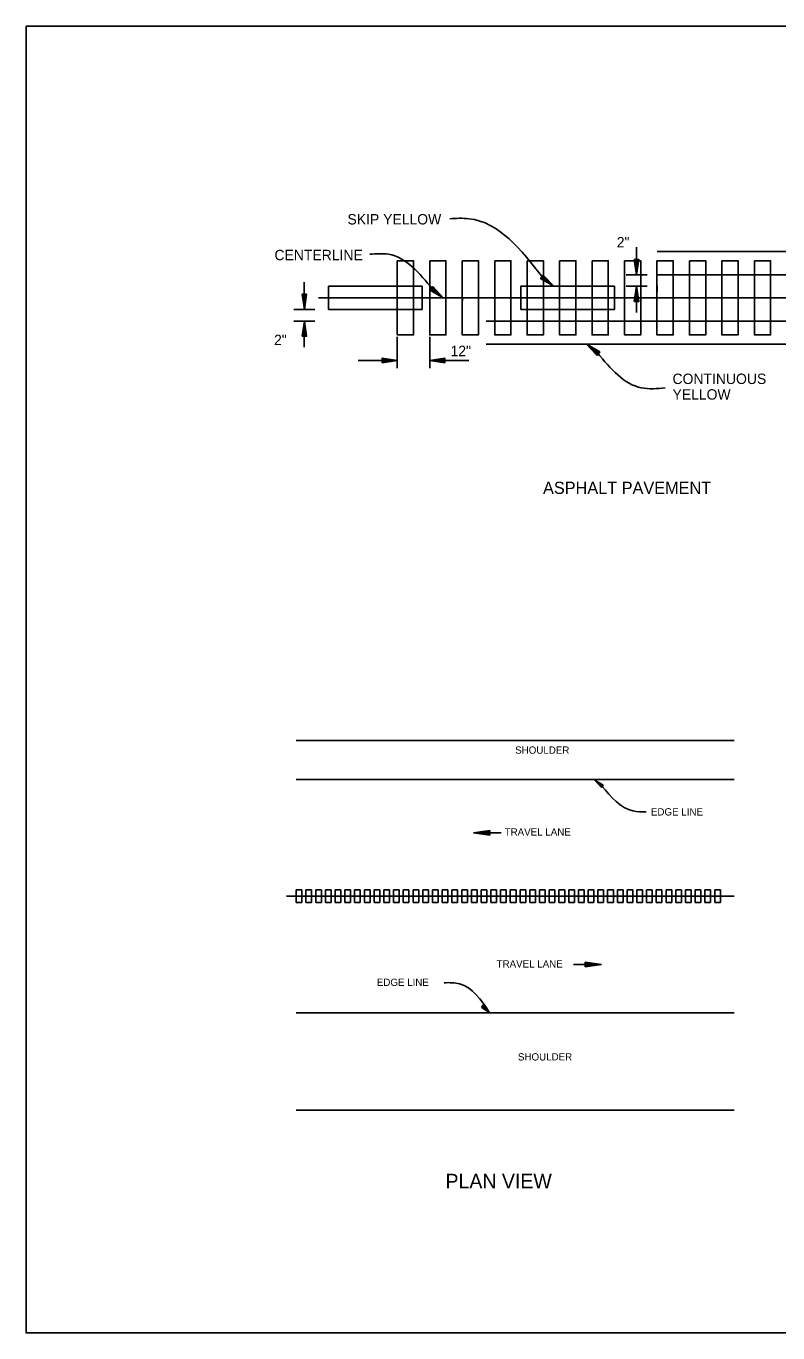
# Model space of a CAD drawing. Extents: x 8229 to 8749, y 14916 to 18021.
# Drawn here: x 8230.8 to 8423.6, y 16130.8 to 16466 of the extents above; entities that cross this region are included whole.
import ezdxf

# ---------------------------------------------------------------- set-up
doc = ezdxf.new("R2010")
doc.units = 0
doc.layers.add('Default', color=7, linetype='Continuous')
doc.layers.add('R_Draft', color=7, linetype='Continuous')

msp = doc.modelspace()

# ---------------------------------------------------------------- linework, layer by layer
at = {"layer": 'Default'}
for p, q in [((8387.32, 16402.27), (8387.32, 16409.3)), ((8386.76, 16406.17), (8387.34, 16402.27)), ((8386.76, 16406.17), (8387.93, 16406.17)), ((8386.85, 16406.17), (8387.34, 16402.92)), ((8386.95, 16406.17), (8387.34, 16403.59)), ((8387.05, 16406.17), (8387.34, 16404.24)), ((8387.15, 16406.17), (8387.34, 16404.9)), ((8387.25, 16406.17), (8387.34, 16405.55)), ((8387.93, 16406.17), (8387.34, 16402.27)), ((8387.53, 16406.17), (8387.34, 16404.9)), ((8387.73, 16406.17), (8387.34, 16403.59)), ((8387.83, 16406.17), (8387.34, 16402.92)), ((8387.63, 16406.17), (8387.34, 16404.24)), ((8387.43, 16406.17), (8387.34, 16405.55)), ((8362.67, 16401.27), (8363.4, 16402.19)), ((8363.21, 16401.95), (8364.54, 16400.52)), ((8363.27, 16402.03), (8365.05, 16400.12)), ((8363.33, 16402.11), (8365.57, 16399.7)), ((8363.4, 16402.19), (8366.08, 16399.29)), ((8384.67, 16402.27), (8390.01, 16402.27)), ((8302.13, 16393.35), (8302.13, 16400.38)), ((8334.37, 16398.3), (8335.1, 16399.21)), ((8334.61, 16398.61), (8335.72, 16397.96)), ((8334.67, 16398.68), (8335.21, 16398.37)), ((8334.79, 16398.83), (8335.21, 16398.37)), ((8334.85, 16398.9), (8335.72, 16397.96)), ((8334.91, 16398.98), (8336.24, 16397.55)), ((8334.97, 16399.06), (8336.75, 16397.15)), ((8335.03, 16399.14), (8337.27, 16396.73)), ((8335.1, 16399.21), (8337.78, 16396.32)), ((8362.67, 16401.27), (8366.08, 16399.29)), ((8362.73, 16401.35), (8365.57, 16399.7)), ((8362.79, 16401.42), (8365.05, 16400.12)), ((8362.85, 16401.5), (8364.54, 16400.52)), ((8362.91, 16401.58), (8364.02, 16400.94)), ((8362.97, 16401.66), (8363.51, 16401.34)), ((8363.09, 16401.8), (8363.51, 16401.34)), ((8363.15, 16401.88), (8364.02, 16400.94)), ((8384.67, 16399.29), (8390.01, 16399.29)), ((8386.76, 16395.39), (8387.34, 16399.29)), ((8386.85, 16395.39), (8387.34, 16398.64)), ((8387.93, 16395.39), (8387.34, 16399.29)), ((8387.83, 16395.39), (8387.34, 16398.64)), ((8301.57, 16397.25), (8302.15, 16393.35)), ((8301.57, 16397.25), (8302.74, 16397.25)), ((8301.66, 16397.25), (8302.15, 16394)), ((8301.76, 16397.25), (8302.15, 16394.67)), ((8301.86, 16397.25), (8302.15, 16395.32)), ((8301.96, 16397.25), (8302.15, 16395.98)), ((8302.06, 16397.25), (8302.15, 16396.63)), ((8302.74, 16397.25), (8302.15, 16393.35)), ((8302.34, 16397.25), (8302.15, 16395.98)), ((8302.54, 16397.25), (8302.15, 16394.67)), ((8302.64, 16397.25), (8302.15, 16394)), ((8302.44, 16397.25), (8302.15, 16395.32)), ((8302.24, 16397.25), (8302.15, 16396.63)), ((8305.76, 16396.32), (8470.2, 16396.32)), ((8334.37, 16398.3), (8337.78, 16396.32)), ((8334.43, 16398.37), (8337.27, 16396.73)), ((8334.49, 16398.45), (8336.75, 16397.15)), ((8334.55, 16398.53), (8336.24, 16397.55)), ((8387.93, 16395.39), (8386.76, 16395.39)), ((8386.95, 16395.39), (8387.34, 16397.97)), ((8387.05, 16395.39), (8387.34, 16397.32)), ((8387.15, 16395.39), (8387.34, 16396.66)), ((8387.25, 16395.39), (8387.34, 16396.01)), ((8387.32, 16392.61), (8387.32, 16395.39)), ((8387.73, 16395.39), (8387.34, 16397.97)), ((8387.63, 16395.39), (8387.34, 16397.32)), ((8387.53, 16395.39), (8387.34, 16396.66)), ((8387.43, 16395.39), (8387.34, 16396.01)), ((8299.48, 16393.35), (8304.82, 16393.35)), ((8299.48, 16390.38), (8304.82, 16390.38)), ((8301.57, 16386.47), (8302.15, 16390.38)), ((8301.66, 16386.47), (8302.15, 16389.72)), ((8301.76, 16386.47), (8302.15, 16389.05)), ((8302.74, 16386.47), (8302.15, 16390.38)), ((8302.64, 16386.47), (8302.15, 16389.72)), ((8302.54, 16386.47), (8302.15, 16389.05)), ((8302.74, 16386.47), (8301.57, 16386.47)), ((8301.86, 16386.47), (8302.15, 16388.4)), ((8301.96, 16386.47), (8302.15, 16387.74)), ((8302.06, 16386.47), (8302.15, 16387.09)), ((8302.13, 16383.69), (8302.13, 16386.47)), ((8302.44, 16386.47), (8302.15, 16388.4)), ((8302.34, 16386.47), (8302.15, 16387.74)), ((8302.24, 16386.47), (8302.15, 16387.09)), ((8325.98, 16378.31), (8325.98, 16386.32)), ((8334.29, 16378.3), (8334.29, 16386.34)), ((8377.94, 16382.45), (8374.53, 16384.43)), ((8377.21, 16381.53), (8374.53, 16384.43)), ((8377.88, 16382.37), (8375.04, 16384.02)), ((8377.27, 16381.61), (8375.04, 16384.02)), ((8377.33, 16381.69), (8375.56, 16383.6)), ((8377.82, 16382.29), (8375.56, 16383.6)), ((8377.76, 16382.22), (8376.07, 16383.2)), ((8377.39, 16381.76), (8376.07, 16383.2)), ((8377.45, 16381.84), (8376.58, 16382.78)), ((8377.69, 16382.14), (8376.58, 16382.78)), ((8377.52, 16381.92), (8377.09, 16382.38)), ((8377.63, 16382.06), (8377.09, 16382.38)), ((8377.94, 16382.45), (8377.21, 16381.53)), ((8322.08, 16380.26), (8315.95, 16380.26)), ((8322.08, 16380.84), (8325.98, 16380.28)), ((8322.08, 16379.67), (8322.08, 16380.84)), ((8322.08, 16380.75), (8325.33, 16380.27)), ((8322.08, 16380.65), (8324.66, 16380.27)), ((8322.08, 16380.55), (8324.01, 16380.27)), ((8322.08, 16380.45), (8323.35, 16380.27)), ((8322.08, 16380.35), (8322.7, 16380.26)), ((8322.08, 16379.67), (8325.98, 16380.28)), ((8322.08, 16380.07), (8323.35, 16380.27)), ((8322.08, 16379.87), (8324.66, 16380.27)), ((8322.08, 16379.77), (8325.33, 16380.27)), ((8322.08, 16379.97), (8324.01, 16380.27)), ((8322.08, 16380.17), (8322.7, 16380.26)), ((8338.2, 16380.83), (8334.29, 16380.27)), ((8338.19, 16379.66), (8334.29, 16380.27)), ((8338.19, 16380.74), (8334.94, 16380.26)), ((8338.19, 16379.76), (8334.94, 16380.26)), ((8338.19, 16380.64), (8335.61, 16380.26)), ((8338.19, 16379.86), (8335.61, 16380.26)), ((8338.19, 16380.54), (8336.26, 16380.26)), ((8338.19, 16379.96), (8336.26, 16380.26)), ((8338.19, 16380.44), (8336.92, 16380.25)), ((8338.19, 16380.06), (8336.92, 16380.25)), ((8338.19, 16380.34), (8337.58, 16380.25)), ((8338.19, 16380.16), (8337.58, 16380.25)), ((8338.2, 16380.83), (8338.19, 16379.66)), ((8344.32, 16380.25), (8338.19, 16380.25))]:
    msp.add_line(p, q, dxfattribs=at)
for points in [[(8230.82, 16466.05), (8748.98, 16466.05), (8748.98, 16130.77), (8230.82, 16130.77)], [(8230.82, 16466.05), (8230.82, 16130.77), (8748.98, 16130.77), (8748.98, 16466.05)], [(8325.98, 16405.83), (8325.98, 16386.81), (8330.14, 16386.81), (8330.14, 16405.83)], [(8334.31, 16405.83), (8334.31, 16386.81), (8338.47, 16386.81), (8338.47, 16405.83)], [(8342.63, 16405.83), (8342.63, 16386.81), (8346.79, 16386.81), (8346.79, 16405.83)], [(8350.95, 16405.83), (8350.95, 16386.81), (8355.11, 16386.81), (8355.11, 16405.83)], [(8359.28, 16405.83), (8359.28, 16386.81), (8363.44, 16386.81), (8363.44, 16405.83)], [(8367.6, 16405.83), (8367.6, 16386.81), (8371.76, 16386.81), (8371.76, 16405.83)], [(8375.92, 16405.83), (8375.92, 16386.81), (8380.08, 16386.81), (8380.08, 16405.83)], [(8384.25, 16405.83), (8384.25, 16386.81), (8388.41, 16386.81), (8388.41, 16405.83)], [(8392.57, 16405.83), (8392.57, 16386.81), (8396.73, 16386.81), (8396.73, 16405.83)], [(8400.89, 16405.83), (8400.89, 16386.81), (8405.05, 16386.81), (8405.05, 16405.83)], [(8409.22, 16405.83), (8409.22, 16386.81), (8413.38, 16386.81), (8413.38, 16405.83)], [(8417.54, 16405.83), (8417.54, 16386.81), (8421.7, 16386.81), (8421.7, 16405.83)]]:
    msp.add_lwpolyline(points, close=True, dxfattribs=at)
for points in [[(8339.42, 16416.64), (8344.32, 16416.64), (8363.3, 16401.52)], [(8318.9, 16407.52), (8323.74, 16407.52), (8335, 16398.55)], [(8394.69, 16373.24), (8388.57, 16373.24), (8377.31, 16382.2)]]:
    msp.add_spline(points, degree=3, dxfattribs=at)
at = {"layer": 'R_Draft'}
for p, q in [((8392.61, 16408.21), (8469.41, 16408.21)), ((8392.61, 16402.27), (8469.41, 16402.27)), ((8308.34, 16399.29), (8308.34, 16393.35)), ((8308.34, 16399.29), (8332.35, 16399.29)), ((8332.35, 16399.29), (8332.35, 16393.35)), ((8357.7, 16399.29), (8357.7, 16393.35)), ((8357.7, 16399.29), (8381.71, 16399.29)), ((8381.71, 16399.29), (8381.71, 16393.35)), ((8392.61, 16399.44), (8392.61, 16397.88)), ((8342.72, 16396.32), (8342.72, 16395.54)), ((8308.34, 16393.35), (8332.35, 16393.35)), ((8357.7, 16393.35), (8381.71, 16393.35)), ((8348.81, 16390.38), (8469.41, 16390.38)), ((8348.81, 16384.43), (8469.41, 16384.43)), ((8300.07, 16282.74), (8412.32, 16282.74)), ((8300.07, 16272.76), (8355.93, 16272.76)), ((8412.32, 16272.76), (8355.93, 16272.76)), ((8378.3, 16270.71), (8376.59, 16272.56)), ((8378.77, 16271.3), (8376.59, 16272.56)), ((8378.34, 16270.76), (8376.91, 16272.3)), ((8378.73, 16271.25), (8376.91, 16272.3)), ((8378.69, 16271.2), (8377.25, 16272.04)), ((8378.38, 16270.81), (8377.25, 16272.04)), ((8378.42, 16270.86), (8377.57, 16271.78)), ((8378.65, 16271.15), (8377.57, 16271.78)), ((8378.61, 16271.1), (8377.9, 16271.51)), ((8378.46, 16270.91), (8377.9, 16271.51)), ((8378.57, 16271.05), (8378.23, 16271.25)), ((8378.49, 16270.96), (8378.23, 16271.25)), ((8378.3, 16270.71), (8378.77, 16271.3)), ((8349.67, 16259.7), (8345.48, 16259.07)), ((8352.61, 16259.07), (8345.48, 16259.07)), ((8349.67, 16258.45), (8345.48, 16259.07)), ((8349.67, 16259.59), (8346.18, 16259.07)), ((8349.67, 16258.54), (8346.18, 16259.07)), ((8349.67, 16259.49), (8346.89, 16259.07)), ((8349.67, 16258.66), (8346.89, 16259.07)), ((8349.67, 16259.38), (8347.59, 16259.07)), ((8349.67, 16258.76), (8347.59, 16259.07)), ((8349.67, 16259.27), (8348.3, 16259.07)), ((8349.67, 16258.86), (8348.3, 16259.07)), ((8349.67, 16259.17), (8349, 16259.07)), ((8349.67, 16258.97), (8349, 16259.07)), ((8349.67, 16259.7), (8349.67, 16258.45)), ((8301.53, 16244.47), (8300.07, 16244.47)), ((8300.07, 16244.47), (8300.07, 16241.15)), ((8301.53, 16244.47), (8301.53, 16241.15)), ((8304.02, 16244.47), (8302.57, 16244.47)), ((8302.57, 16244.47), (8302.57, 16241.15)), ((8304.02, 16244.47), (8304.02, 16241.15)), ((8306.52, 16244.47), (8305.06, 16244.47)), ((8305.06, 16244.47), (8305.06, 16241.15)), ((8306.52, 16244.47), (8306.52, 16241.15)), ((8309.02, 16244.47), (8307.56, 16244.47)), ((8307.56, 16244.47), (8307.56, 16241.15)), ((8309.02, 16244.47), (8309.02, 16241.15)), ((8311.51, 16244.47), (8310.05, 16244.47)), ((8310.05, 16244.47), (8310.05, 16241.15)), ((8311.51, 16244.47), (8311.51, 16241.15)), ((8314.01, 16244.47), (8312.55, 16244.47)), ((8312.55, 16244.47), (8312.55, 16241.15)), ((8314.01, 16244.47), (8314.01, 16241.15)), ((8316.5, 16244.47), (8315.04, 16244.47)), ((8315.04, 16244.47), (8315.04, 16241.15)), ((8316.5, 16244.47), (8316.5, 16241.15)), ((8319, 16244.47), (8317.54, 16244.47)), ((8317.54, 16244.47), (8317.54, 16241.15)), ((8319, 16244.47), (8319, 16241.15)), ((8321.49, 16244.47), (8320.03, 16244.47)), ((8320.03, 16244.47), (8320.03, 16241.15)), ((8321.49, 16244.47), (8321.49, 16241.15)), ((8323.99, 16244.47), (8322.53, 16244.47)), ((8322.53, 16244.47), (8322.53, 16241.15)), ((8323.99, 16244.47), (8323.99, 16241.15)), ((8326.48, 16244.47), (8325.02, 16244.47)), ((8325.02, 16244.47), (8325.02, 16241.15)), ((8326.48, 16244.47), (8326.48, 16241.15)), ((8328.98, 16244.47), (8327.52, 16244.47)), ((8327.52, 16244.47), (8327.52, 16241.15)), ((8328.98, 16244.47), (8328.98, 16241.15)), ((8331.47, 16244.47), (8330.01, 16244.47)), ((8330.01, 16244.47), (8330.01, 16241.15)), ((8331.47, 16244.47), (8331.47, 16241.15)), ((8333.97, 16244.47), (8332.51, 16244.47)), ((8332.51, 16244.47), (8332.51, 16241.15)), ((8333.97, 16244.47), (8333.97, 16241.15)), ((8336.46, 16244.47), (8335, 16244.47)), ((8335, 16244.47), (8335, 16241.15)), ((8336.46, 16244.47), (8336.46, 16241.15)), ((8338.96, 16244.47), (8337.5, 16244.47)), ((8337.5, 16244.47), (8337.5, 16241.15)), ((8338.96, 16244.47), (8338.96, 16241.15)), ((8341.45, 16244.47), (8339.99, 16244.47)), ((8339.99, 16244.47), (8339.99, 16241.15)), ((8341.45, 16244.47), (8341.45, 16241.15)), ((8343.95, 16244.47), (8342.49, 16244.47)), ((8342.49, 16244.47), (8342.49, 16241.15)), ((8343.95, 16244.47), (8343.95, 16241.15)), ((8346.44, 16244.47), (8344.98, 16244.47)), ((8344.98, 16244.47), (8344.98, 16241.15)), ((8346.44, 16244.47), (8346.44, 16241.15)), ((8348.94, 16244.47), (8347.48, 16244.47)), ((8347.48, 16244.47), (8347.48, 16241.15)), ((8348.94, 16244.47), (8348.94, 16241.15)), ((8351.43, 16244.47), (8349.97, 16244.47)), ((8349.97, 16244.47), (8349.97, 16241.15)), ((8351.43, 16244.47), (8351.43, 16241.15)), ((8353.93, 16244.47), (8352.47, 16244.47)), ((8352.47, 16244.47), (8352.47, 16241.15)), ((8353.93, 16244.47), (8353.93, 16241.15)), ((8356.42, 16244.47), (8354.96, 16244.47)), ((8354.96, 16244.47), (8354.96, 16241.15)), ((8356.42, 16244.47), (8356.42, 16241.15)), ((8358.92, 16244.47), (8357.46, 16244.47)), ((8357.46, 16244.47), (8357.46, 16241.15)), ((8358.92, 16244.47), (8358.92, 16241.15)), ((8361.41, 16244.47), (8359.95, 16244.47)), ((8359.95, 16244.47), (8359.95, 16241.15)), ((8361.41, 16244.47), (8361.41, 16241.15)), ((8363.91, 16244.47), (8362.45, 16244.47)), ((8362.45, 16244.47), (8362.45, 16241.15)), ((8363.91, 16244.47), (8363.91, 16241.15)), ((8366.4, 16244.47), (8364.95, 16244.47)), ((8364.95, 16244.47), (8364.95, 16241.15)), ((8366.4, 16244.47), (8366.4, 16241.15)), ((8368.9, 16244.47), (8367.44, 16244.47)), ((8367.44, 16244.47), (8367.44, 16241.15)), ((8368.9, 16244.47), (8368.9, 16241.15)), ((8371.4, 16244.47), (8369.94, 16244.47)), ((8369.94, 16244.47), (8369.94, 16241.15)), ((8371.4, 16244.47), (8371.4, 16241.15)), ((8373.89, 16244.47), (8372.43, 16244.47)), ((8372.43, 16244.47), (8372.43, 16241.15)), ((8373.89, 16244.47), (8373.89, 16241.15)), ((8376.39, 16244.47), (8374.93, 16244.47)), ((8374.93, 16244.47), (8374.93, 16241.15)), ((8376.39, 16244.47), (8376.39, 16241.15)), ((8378.88, 16244.47), (8377.42, 16244.47)), ((8377.42, 16244.47), (8377.42, 16241.15)), ((8378.88, 16244.47), (8378.88, 16241.15)), ((8381.38, 16244.47), (8379.92, 16244.47)), ((8379.92, 16244.47), (8379.92, 16241.15)), ((8381.38, 16244.47), (8381.38, 16241.15)), ((8383.87, 16244.47), (8382.41, 16244.47)), ((8382.41, 16244.47), (8382.41, 16241.15)), ((8383.87, 16244.47), (8383.87, 16241.15)), ((8386.37, 16244.47), (8384.91, 16244.47)), ((8384.91, 16244.47), (8384.91, 16241.15)), ((8386.37, 16244.47), (8386.37, 16241.15)), ((8388.86, 16244.47), (8387.4, 16244.47)), ((8387.4, 16244.47), (8387.4, 16241.15)), ((8388.86, 16244.47), (8388.86, 16241.15)), ((8391.36, 16244.47), (8389.9, 16244.47)), ((8389.9, 16244.47), (8389.9, 16241.15)), ((8391.36, 16244.47), (8391.36, 16241.15)), ((8393.85, 16244.47), (8392.39, 16244.47)), ((8392.39, 16244.47), (8392.39, 16241.15)), ((8393.85, 16244.47), (8393.85, 16241.15)), ((8396.35, 16244.47), (8394.89, 16244.47)), ((8394.89, 16244.47), (8394.89, 16241.15)), ((8396.35, 16244.47), (8396.35, 16241.15)), ((8398.84, 16244.47), (8397.38, 16244.47)), ((8397.38, 16244.47), (8397.38, 16241.15)), ((8398.84, 16244.47), (8398.84, 16241.15)), ((8401.34, 16244.47), (8399.88, 16244.47)), ((8399.88, 16244.47), (8399.88, 16241.15)), ((8401.34, 16244.47), (8401.34, 16241.15)), ((8403.83, 16244.47), (8402.37, 16244.47)), ((8402.37, 16244.47), (8402.37, 16241.15)), ((8403.83, 16244.47), (8403.83, 16241.15)), ((8406.33, 16244.47), (8404.87, 16244.47)), ((8404.87, 16244.47), (8404.87, 16241.15)), ((8406.33, 16244.47), (8406.33, 16241.15)), ((8408.82, 16244.47), (8407.36, 16244.47)), ((8407.36, 16244.47), (8407.36, 16241.15)), ((8408.82, 16244.47), (8408.82, 16241.15)), ((8297.6, 16242.81), (8412.32, 16242.81)), ((8300.07, 16241.15), (8301.53, 16241.15)), ((8302.57, 16241.15), (8304.02, 16241.15)), ((8305.06, 16241.15), (8306.52, 16241.15)), ((8307.56, 16241.15), (8309.02, 16241.15)), ((8310.05, 16241.15), (8311.51, 16241.15)), ((8312.55, 16241.15), (8314.01, 16241.15)), ((8315.04, 16241.15), (8316.5, 16241.15)), ((8317.54, 16241.15), (8319, 16241.15)), ((8320.03, 16241.15), (8321.49, 16241.15)), ((8322.53, 16241.15), (8323.99, 16241.15)), ((8325.02, 16241.15), (8326.48, 16241.15)), ((8327.52, 16241.15), (8328.98, 16241.15)), ((8330.01, 16241.15), (8331.47, 16241.15)), ((8332.51, 16241.15), (8333.97, 16241.15)), ((8335, 16241.15), (8336.46, 16241.15)), ((8337.5, 16241.15), (8338.96, 16241.15)), ((8339.99, 16241.15), (8341.45, 16241.15)), ((8342.49, 16241.15), (8343.95, 16241.15)), ((8344.98, 16241.15), (8346.44, 16241.15)), ((8347.48, 16241.15), (8348.94, 16241.15)), ((8349.97, 16241.15), (8351.43, 16241.15)), ((8352.47, 16241.15), (8353.93, 16241.15)), ((8354.96, 16241.15), (8356.42, 16241.15)), ((8357.46, 16241.15), (8358.92, 16241.15)), ((8359.95, 16241.15), (8361.41, 16241.15)), ((8362.45, 16241.15), (8363.91, 16241.15)), ((8364.95, 16241.15), (8366.4, 16241.15)), ((8367.44, 16241.15), (8368.9, 16241.15)), ((8369.94, 16241.15), (8371.4, 16241.15)), ((8372.43, 16241.15), (8373.89, 16241.15)), ((8374.93, 16241.15), (8376.39, 16241.15)), ((8377.42, 16241.15), (8378.88, 16241.15)), ((8379.92, 16241.15), (8381.38, 16241.15)), ((8382.41, 16241.15), (8383.87, 16241.15)), ((8384.91, 16241.15), (8386.37, 16241.15)), ((8387.4, 16241.15), (8388.86, 16241.15)), ((8389.9, 16241.15), (8391.36, 16241.15)), ((8392.39, 16241.15), (8393.85, 16241.15)), ((8394.89, 16241.15), (8396.35, 16241.15)), ((8397.38, 16241.15), (8398.84, 16241.15)), ((8399.88, 16241.15), (8401.34, 16241.15)), ((8402.37, 16241.15), (8403.83, 16241.15)), ((8404.87, 16241.15), (8406.33, 16241.15)), ((8407.36, 16241.15), (8408.82, 16241.15)), ((8371.2, 16225.29), (8378.33, 16225.29)), ((8374.14, 16225.91), (8378.33, 16225.29)), ((8374.14, 16224.66), (8374.14, 16225.91)), ((8374.14, 16225.81), (8377.63, 16225.29)), ((8374.14, 16225.7), (8376.92, 16225.29)), ((8374.14, 16225.6), (8376.22, 16225.29)), ((8374.14, 16225.49), (8375.51, 16225.29)), ((8374.14, 16225.39), (8374.81, 16225.29)), ((8374.14, 16224.66), (8378.33, 16225.29)), ((8374.14, 16225.09), (8375.51, 16225.29)), ((8374.14, 16224.87), (8376.92, 16225.29)), ((8374.14, 16224.76), (8377.63, 16225.29)), ((8374.14, 16224.97), (8376.22, 16225.29)), ((8374.14, 16225.18), (8374.81, 16225.29)), ((8348.1, 16214.9), (8347.58, 16214.36)), ((8347.58, 16214.36), (8349.64, 16212.89)), ((8347.63, 16214.41), (8349.34, 16213.18)), ((8347.67, 16214.45), (8349.03, 16213.48)), ((8347.72, 16214.49), (8348.73, 16213.77)), ((8347.76, 16214.54), (8348.43, 16214.06)), ((8347.8, 16214.59), (8348.13, 16214.36)), ((8347.88, 16214.67), (8348.13, 16214.36)), ((8347.93, 16214.71), (8348.43, 16214.06)), ((8347.97, 16214.76), (8348.73, 16213.77)), ((8348.02, 16214.8), (8349.03, 16213.48)), ((8348.06, 16214.85), (8349.34, 16213.18)), ((8348.1, 16214.9), (8349.64, 16212.89)), ((8300.07, 16212.87), (8355.93, 16212.87)), ((8412.32, 16212.87), (8355.93, 16212.87)), ((8384.91, 16212.87), (8412.32, 16212.87)), ((8300.07, 16187.92), (8412.32, 16187.92))]:
    msp.add_line(p, q, dxfattribs=at)
for points in [[(8386.74, 16406.17), (8387.91, 16406.17), (8387.34, 16402.27)], [(8386.74, 16395.39), (8387.91, 16395.39), (8387.34, 16399.29)], [(8301.55, 16386.47), (8302.72, 16386.47), (8302.15, 16390.38)], [(8377.64, 16382.62), (8376.98, 16381.78), (8374.53, 16384.43)], [(8322.08, 16379.67), (8322.08, 16380.85), (8325.98, 16380.28)], [(8338.19, 16379.66), (8338.19, 16380.84), (8334.29, 16380.27)]]:
    msp.add_lwpolyline(points, close=True, dxfattribs=at)
for points in [[(8389.77, 16264.45), (8386.39, 16264.7), (8378.44, 16271.03)], [(8337.97, 16220.61), (8341.95, 16220.34), (8349.64, 16212.89)]]:
    msp.add_spline(points, degree=3, dxfattribs=at)

# ---------------------------------------------------------------- texts
at = {"layer": 'Default'}
for s, height, p in [('SKIP YELLOW', 2.6734, (8313.21, 16415.16)), ('CENTERLINE', 2.673, (8294.49, 16405.98)), ('2"', 2.673, (8382.25, 16409.27)), ('2"', 2.673, (8294.38, 16384.21)), ('12"', 2.673, (8339.64, 16381.36)), ('CONTINUOUS ', 2.6734, (8396.55, 16374.22)), ('YELLOW', 2.673, (8396.55, 16370.21)), ('ASPHALT PAVEMENT', 3.119, (8363.35, 16346.03))]:
    msp.add_text(s, height=height, dxfattribs=at).set_placement(p)
at = {"layer": 'R_Draft'}
for s, height, p in [('SHOULDER', 1.871, (8356.21, 16279.36)), ('EDGE LINE', 1.871, (8391.01, 16263.51)), ('TRAVEL LANE', 1.8714, (8353.51, 16258.35)), ('TRAVEL LANE', 1.8714, (8351.44, 16224.51)), ('EDGE LINE', 1.871, (8320.73, 16219.78)), ('SHOULDER', 1.871, (8356.92, 16200.65)), ('PLAN VIEW ', 3.743, (8338.34, 16167.83))]:
    msp.add_text(s, height=height, dxfattribs=at).set_placement(p)

doc.saveas('drawing.dxf')
